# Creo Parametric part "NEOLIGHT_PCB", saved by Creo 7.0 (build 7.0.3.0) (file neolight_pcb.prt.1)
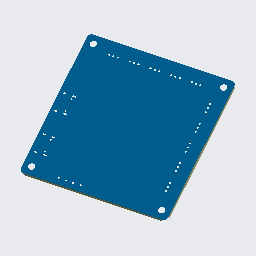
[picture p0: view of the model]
Units: millimeter Newton Second (mmNs); MM, TONNE, SECS

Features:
  1. coordinate system "NEOLIGHT_PCB"
  2. imported feature "Import Feature id 5"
